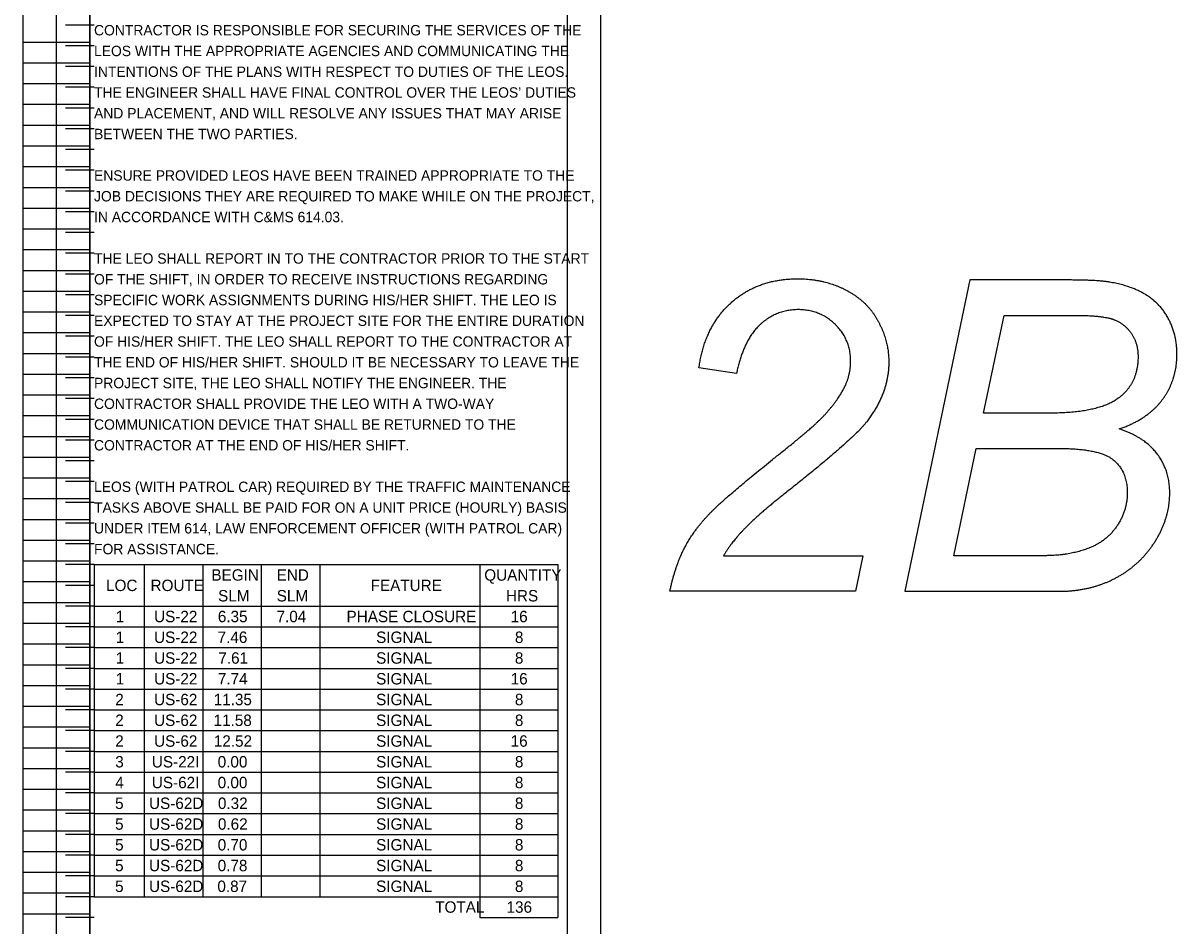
# Model space of a CAD drawing. Extents: x 12522 to 13018, y 1124 to 1902.
# Drawn here: x 12563.34 to 12578.9, y 1732.59 to 1744.77 of the extents above; entities that cross this region are included whole.
import ezdxf

# ---------------------------------------------------------------- set-up
doc = ezdxf.new("R2010")
doc.units = 0
for name, color, linetype in [('SC_Scratch1', 7, 'Continuous'), ('SH_Data', 7, 'Continuous'), ('SH_Text', 7, 'Continuous')]:
    doc.layers.add(name, color=color, linetype=linetype)

msp = doc.modelspace()

# ---------------------------------------------------------------- linework, layer by layer
at = {"layer": 'SC_Scratch1'}
for p, q in [((12564.236, 1769.381), (12564.236, 1728.831)), ((12563.336, 1728.831), (12563.336, 1748.991)), ((12563.336, 1728.831), (12563.336, 1748.991)), ((12564.236, 1728.831), (12564.236, 1748.991)), ((12564.236, 1728.831), (12564.236, 1748.991)), ((12564.293, 1744.741), (12563.909, 1744.741)), ((12563.336, 1744.511), (12564.236, 1744.511)), ((12563.336, 1744.511), (12564.236, 1744.511)), ((12564.293, 1744.461), (12563.909, 1744.461)), ((12563.336, 1744.231), (12564.236, 1744.231)), ((12563.336, 1744.231), (12564.236, 1744.231)), ((12564.293, 1744.181), (12563.909, 1744.181)), ((12563.336, 1743.951), (12564.236, 1743.951)), ((12563.336, 1743.951), (12564.236, 1743.951)), ((12564.293, 1743.901), (12563.909, 1743.901)), ((12563.336, 1743.671), (12564.236, 1743.671)), ((12563.336, 1743.671), (12564.236, 1743.671)), ((12564.293, 1743.621), (12563.909, 1743.621)), ((12563.336, 1743.391), (12564.236, 1743.391)), ((12563.336, 1743.391), (12564.236, 1743.391)), ((12564.293, 1743.341), (12563.909, 1743.341)), ((12563.336, 1743.111), (12564.236, 1743.111)), ((12563.336, 1743.111), (12564.236, 1743.111)), ((12564.293, 1743.061), (12563.909, 1743.061)), ((12563.336, 1742.831), (12564.236, 1742.831)), ((12563.336, 1742.831), (12564.236, 1742.831)), ((12564.293, 1742.781), (12563.909, 1742.781)), ((12563.336, 1742.551), (12564.236, 1742.551)), ((12563.336, 1742.551), (12564.236, 1742.551)), ((12564.293, 1742.501), (12563.909, 1742.501)), ((12563.336, 1742.271), (12564.236, 1742.271)), ((12563.336, 1742.271), (12564.236, 1742.271)), ((12564.293, 1742.221), (12563.909, 1742.221)), ((12563.336, 1741.991), (12564.236, 1741.991)), ((12563.336, 1741.991), (12564.236, 1741.991)), ((12564.293, 1741.941), (12563.909, 1741.941)), ((12563.336, 1741.711), (12564.236, 1741.711)), ((12563.336, 1741.711), (12564.236, 1741.711)), ((12564.293, 1741.661), (12563.909, 1741.661)), ((12563.336, 1741.431), (12564.236, 1741.431)), ((12563.336, 1741.431), (12564.236, 1741.431)), ((12564.293, 1741.381), (12563.909, 1741.381)), ((12563.336, 1741.151), (12564.236, 1741.151)), ((12563.336, 1741.151), (12564.236, 1741.151)), ((12564.293, 1741.101), (12563.909, 1741.101)), ((12563.336, 1740.871), (12564.236, 1740.871)), ((12563.336, 1740.871), (12564.236, 1740.871)), ((12564.293, 1740.821), (12563.909, 1740.821)), ((12563.336, 1740.591), (12564.236, 1740.591)), ((12563.336, 1740.591), (12564.236, 1740.591)), ((12564.293, 1740.541), (12563.909, 1740.541)), ((12563.336, 1740.311), (12564.236, 1740.311)), ((12563.336, 1740.311), (12564.236, 1740.311)), ((12564.293, 1740.261), (12563.909, 1740.261)), ((12563.336, 1740.031), (12564.236, 1740.031)), ((12563.336, 1740.031), (12564.236, 1740.031)), ((12572.959, 1740.039), (12572.453, 1740.114)), ((12572.959, 1740.039), (12572.453, 1740.114)), ((12564.293, 1739.981), (12563.909, 1739.981)), ((12563.336, 1739.751), (12564.236, 1739.751)), ((12563.336, 1739.751), (12564.236, 1739.751)), ((12564.293, 1739.701), (12563.909, 1739.701)), ((12563.336, 1739.471), (12564.236, 1739.471)), ((12563.336, 1739.471), (12564.236, 1739.471)), ((12564.293, 1739.421), (12563.909, 1739.421)), ((12563.336, 1739.191), (12564.236, 1739.191)), ((12563.336, 1739.191), (12564.236, 1739.191)), ((12564.293, 1739.141), (12563.909, 1739.141)), ((12563.336, 1738.911), (12564.236, 1738.911)), ((12563.336, 1738.911), (12564.236, 1738.911)), ((12564.293, 1738.861), (12563.909, 1738.861)), ((12563.336, 1738.631), (12564.236, 1738.631)), ((12563.336, 1738.631), (12564.236, 1738.631)), ((12564.293, 1738.581), (12563.909, 1738.581)), ((12563.336, 1738.351), (12564.236, 1738.351)), ((12563.336, 1738.351), (12564.236, 1738.351)), ((12564.293, 1738.301), (12563.909, 1738.301)), ((12563.336, 1738.071), (12564.236, 1738.071)), ((12563.336, 1738.071), (12564.236, 1738.071)), ((12564.293, 1738.021), (12563.909, 1738.021)), ((12563.336, 1737.791), (12564.236, 1737.791)), ((12563.336, 1737.791), (12564.236, 1737.791)), ((12564.293, 1737.741), (12563.909, 1737.741)), ((12563.336, 1737.511), (12564.236, 1737.511)), ((12563.336, 1737.511), (12564.236, 1737.511)), ((12564.293, 1737.461), (12563.909, 1737.461)), ((12563.336, 1737.231), (12564.236, 1737.231)), ((12563.336, 1737.231), (12564.236, 1737.231)), ((12564.293, 1737.181), (12563.909, 1737.181)), ((12563.336, 1736.951), (12564.236, 1736.951)), ((12563.336, 1736.951), (12564.236, 1736.951)), ((12564.293, 1736.901), (12563.909, 1736.901)), ((12563.336, 1736.671), (12564.236, 1736.671)), ((12563.336, 1736.671), (12564.236, 1736.671)), ((12564.293, 1736.621), (12563.909, 1736.621)), ((12563.336, 1736.391), (12564.236, 1736.391)), ((12563.336, 1736.391), (12564.236, 1736.391)), ((12564.293, 1736.341), (12563.909, 1736.341)), ((12563.336, 1736.111), (12564.236, 1736.111)), ((12563.336, 1736.111), (12564.236, 1736.111)), ((12564.293, 1736.061), (12563.909, 1736.061)), ((12563.336, 1735.831), (12564.236, 1735.831)), ((12563.336, 1735.831), (12564.236, 1735.831)), ((12564.293, 1735.781), (12563.909, 1735.781)), ((12563.336, 1735.551), (12564.236, 1735.551)), ((12563.336, 1735.551), (12564.236, 1735.551)), ((12564.293, 1735.501), (12563.909, 1735.501)), ((12563.336, 1735.271), (12564.236, 1735.271)), ((12563.336, 1735.271), (12564.236, 1735.271)), ((12564.293, 1735.221), (12563.909, 1735.221)), ((12563.336, 1734.991), (12564.236, 1734.991)), ((12563.336, 1734.991), (12564.236, 1734.991)), ((12564.293, 1734.941), (12563.909, 1734.941)), ((12563.336, 1734.711), (12564.236, 1734.711)), ((12563.336, 1734.711), (12564.236, 1734.711)), ((12564.293, 1734.661), (12563.909, 1734.661)), ((12563.336, 1734.431), (12564.236, 1734.431)), ((12563.336, 1734.431), (12564.236, 1734.431)), ((12564.293, 1734.381), (12563.909, 1734.381)), ((12563.336, 1734.151), (12564.236, 1734.151)), ((12563.336, 1734.151), (12564.236, 1734.151)), ((12564.293, 1734.101), (12563.909, 1734.101)), ((12563.336, 1733.871), (12564.236, 1733.871)), ((12563.336, 1733.871), (12564.236, 1733.871)), ((12564.293, 1733.821), (12563.909, 1733.821)), ((12563.336, 1733.591), (12564.236, 1733.591)), ((12563.336, 1733.591), (12564.236, 1733.591)), ((12564.293, 1733.541), (12563.909, 1733.541)), ((12563.336, 1733.311), (12564.236, 1733.311)), ((12563.336, 1733.311), (12564.236, 1733.311)), ((12564.293, 1733.261), (12563.909, 1733.261)), ((12563.336, 1733.031), (12564.236, 1733.031)), ((12563.336, 1733.031), (12564.236, 1733.031)), ((12564.293, 1732.981), (12563.909, 1732.981)), ((12563.336, 1732.751), (12564.236, 1732.751)), ((12563.336, 1732.751), (12564.236, 1732.751)), ((12564.293, 1732.701), (12563.909, 1732.701))]:
    msp.add_line(p, q, dxfattribs=at)
for points in [[(12563.786, 1748.991), (12571.126, 1748.991), (12571.126, 1728.831), (12563.786, 1728.831)], [(12564.236, 1748.991), (12570.676, 1748.991), (12570.676, 1728.831), (12564.236, 1728.831)], [(12564.236, 1748.991), (12570.676, 1748.991), (12570.676, 1728.831), (12564.236, 1728.831)]]:
    msp.add_lwpolyline(points, close=True, dxfattribs=at)
for points in [[(12577.45, 1741.301), (12576.109, 1741.301), (12575.232, 1737.101), (12577.313, 1737.101)], [(12577.45, 1741.301), (12576.109, 1741.301), (12575.232, 1737.101), (12577.313, 1737.101)], [(12577.188, 1739.505), (12576.293, 1739.505), (12576.568, 1740.824), (12577.507, 1740.824)], [(12577.188, 1739.505), (12576.293, 1739.505), (12576.568, 1740.824), (12577.507, 1740.824)], [(12576.883, 1737.578), (12575.891, 1737.578), (12576.193, 1739.028), (12577.31, 1739.028)], [(12576.883, 1737.578), (12575.891, 1737.578), (12576.193, 1739.028), (12577.31, 1739.028)], [(12572.785, 1737.578), (12574.665, 1737.578), (12574.565, 1737.101), (12572.06, 1737.101)], [(12572.785, 1737.578), (12574.665, 1737.578), (12574.565, 1737.101), (12572.06, 1737.101)]]:
    msp.add_lwpolyline(points, dxfattribs=at)
for points in [[(12572.887, 1740.995), (12573.247, 1741.317), (12573.782, 1741.317)], [(12572.887, 1740.995), (12573.247, 1741.317), (12573.782, 1741.317)], [(12573.782, 1741.317), (12574.141, 1741.317), (12574.431, 1741.168)], [(12573.782, 1741.317), (12574.141, 1741.317), (12574.431, 1741.168)], [(12577.994, 1741.272), (12577.816, 1741.301), (12577.45, 1741.301)], [(12577.994, 1741.272), (12577.816, 1741.301), (12577.45, 1741.301)], [(12578.483, 1741.101), (12578.283, 1741.223), (12577.994, 1741.272)], [(12578.483, 1741.101), (12578.283, 1741.223), (12577.994, 1741.272)], [(12574.431, 1741.168), (12574.722, 1741.019), (12574.868, 1740.75)], [(12574.431, 1741.168), (12574.722, 1741.019), (12574.868, 1740.75)], [(12578.791, 1740.769), (12578.682, 1740.98), (12578.483, 1741.101)], [(12578.791, 1740.769), (12578.682, 1740.98), (12578.483, 1741.101)], [(12572.453, 1740.114), (12572.528, 1740.672), (12572.887, 1740.995)], [(12572.453, 1740.114), (12572.528, 1740.672), (12572.887, 1740.995)], [(12573.791, 1740.901), (12573.495, 1740.901), (12573.274, 1740.696)], [(12573.791, 1740.901), (12573.495, 1740.901), (12573.274, 1740.696)], [(12574.294, 1740.699), (12574.089, 1740.901), (12573.791, 1740.901)], [(12574.294, 1740.699), (12574.089, 1740.901), (12573.791, 1740.901)], [(12577.507, 1740.824), (12577.909, 1740.824), (12578.055, 1740.765)], [(12577.507, 1740.824), (12577.909, 1740.824), (12578.055, 1740.765)], [(12573.274, 1740.696), (12573.054, 1740.491), (12572.959, 1740.039)], [(12573.274, 1740.696), (12573.054, 1740.491), (12572.959, 1740.039)], [(12574.499, 1740.208), (12574.499, 1740.497), (12574.294, 1740.699)], [(12574.499, 1740.208), (12574.499, 1740.497), (12574.294, 1740.699)], [(12574.868, 1740.75), (12575.014, 1740.481), (12575.014, 1740.194)], [(12574.868, 1740.75), (12575.014, 1740.481), (12575.014, 1740.194)], [(12578.055, 1740.765), (12578.201, 1740.706), (12578.288, 1740.577)], [(12578.055, 1740.765), (12578.201, 1740.706), (12578.288, 1740.577)], [(12578.901, 1740.303), (12578.901, 1740.558), (12578.791, 1740.769)], [(12578.901, 1740.303), (12578.901, 1740.558), (12578.791, 1740.769)], [(12578.288, 1740.577), (12578.376, 1740.447), (12578.376, 1740.269)], [(12578.288, 1740.577), (12578.376, 1740.447), (12578.376, 1740.269)], [(12574.433, 1739.89), (12574.499, 1740.036), (12574.499, 1740.208)], [(12574.433, 1739.89), (12574.499, 1740.036), (12574.499, 1740.208)], [(12575.014, 1740.194), (12575.014, 1739.776), (12574.716, 1739.389)], [(12575.014, 1740.194), (12575.014, 1739.776), (12574.716, 1739.389)], [(12578.376, 1740.269), (12578.376, 1739.896), (12578.102, 1739.7)], [(12578.376, 1740.269), (12578.376, 1739.896), (12578.102, 1739.7)], [(12578.709, 1739.692), (12578.901, 1739.956), (12578.901, 1740.303)], [(12578.709, 1739.692), (12578.901, 1739.956), (12578.901, 1740.303)], [(12574.121, 1739.452), (12574.335, 1739.676), (12574.433, 1739.89)], [(12574.121, 1739.452), (12574.335, 1739.676), (12574.433, 1739.89)], [(12578.102, 1739.7), (12577.829, 1739.505), (12577.188, 1739.505)], [(12578.102, 1739.7), (12577.829, 1739.505), (12577.188, 1739.505)], [(12578.123, 1739.291), (12578.517, 1739.428), (12578.709, 1739.692)], [(12578.123, 1739.291), (12578.517, 1739.428), (12578.709, 1739.692)], [(12573.564, 1738.974), (12573.971, 1739.298), (12574.121, 1739.452)], [(12573.564, 1738.974), (12573.971, 1739.298), (12574.121, 1739.452)], [(12574.716, 1739.389), (12574.533, 1739.149), (12573.639, 1738.442)], [(12574.716, 1739.389), (12574.533, 1739.149), (12573.639, 1738.442)], [(12578.635, 1738.954), (12578.465, 1739.179), (12578.123, 1739.291)], [(12578.635, 1738.954), (12578.465, 1739.179), (12578.123, 1739.291)], [(12572.659, 1738.211), (12572.894, 1738.439), (12573.564, 1738.974)], [(12572.659, 1738.211), (12572.894, 1738.439), (12573.564, 1738.974)], [(12577.31, 1739.028), (12577.853, 1739.028), (12578.042, 1738.875)], [(12577.31, 1739.028), (12577.853, 1739.028), (12578.042, 1738.875)], [(12578.804, 1738.429), (12578.804, 1738.73), (12578.635, 1738.954)], [(12578.804, 1738.429), (12578.804, 1738.73), (12578.635, 1738.954)], [(12578.042, 1738.875), (12578.231, 1738.722), (12578.231, 1738.427)], [(12578.042, 1738.875), (12578.231, 1738.722), (12578.231, 1738.427)], [(12573.639, 1738.442), (12573.255, 1738.139), (12573.067, 1737.944)], [(12573.639, 1738.442), (12573.255, 1738.139), (12573.067, 1737.944)], [(12578.231, 1738.427), (12578.231, 1738.23), (12578.133, 1738.05)], [(12578.231, 1738.427), (12578.231, 1738.23), (12578.133, 1738.05)], [(12578.601, 1737.765), (12578.804, 1738.083), (12578.804, 1738.429)], [(12578.601, 1737.765), (12578.804, 1738.083), (12578.804, 1738.429)], [(12572.282, 1737.73), (12572.424, 1737.984), (12572.659, 1738.211)], [(12572.282, 1737.73), (12572.424, 1737.984), (12572.659, 1738.211)], [(12578.133, 1738.05), (12578.035, 1737.87), (12577.863, 1737.759)], [(12578.133, 1738.05), (12578.035, 1737.87), (12577.863, 1737.759)], [(12573.067, 1737.944), (12572.879, 1737.75), (12572.785, 1737.578)], [(12573.067, 1737.944), (12572.879, 1737.75), (12572.785, 1737.578)], [(12572.06, 1737.101), (12572.14, 1737.476), (12572.282, 1737.73)], [(12572.06, 1737.101), (12572.14, 1737.476), (12572.282, 1737.73)], [(12577.863, 1737.759), (12577.691, 1737.649), (12577.415, 1737.604)], [(12577.863, 1737.759), (12577.691, 1737.649), (12577.415, 1737.604)], [(12578.062, 1737.274), (12578.397, 1737.447), (12578.601, 1737.765)], [(12578.062, 1737.274), (12578.397, 1737.447), (12578.601, 1737.765)], [(12577.415, 1737.604), (12577.278, 1737.578), (12576.883, 1737.578)], [(12577.415, 1737.604), (12577.278, 1737.578), (12576.883, 1737.578)], [(12577.313, 1737.101), (12577.726, 1737.101), (12578.062, 1737.274)], [(12577.313, 1737.101), (12577.726, 1737.101), (12578.062, 1737.274)]]:
    msp.add_open_spline(points, degree=2, dxfattribs=at)
at = {"layer": 'SH_Data'}
for p, q in [((12564.293, 1737.461), (12570.551, 1737.461)), ((12564.293, 1737.461), (12564.293, 1732.981)), ((12564.968, 1737.461), (12564.968, 1732.981)), ((12565.759, 1737.461), (12565.759, 1732.981)), ((12566.549, 1737.461), (12566.549, 1732.981)), ((12567.34, 1737.461), (12567.34, 1732.981)), ((12569.497, 1737.461), (12569.497, 1732.701)), ((12570.551, 1737.461), (12570.551, 1732.701)), ((12564.293, 1736.901), (12570.551, 1736.901)), ((12564.293, 1736.621), (12570.551, 1736.621)), ((12564.293, 1736.341), (12570.551, 1736.341)), ((12564.293, 1736.061), (12570.551, 1736.061)), ((12564.293, 1735.781), (12570.551, 1735.781)), ((12564.293, 1735.501), (12570.551, 1735.501)), ((12564.293, 1735.221), (12570.551, 1735.221)), ((12564.293, 1734.941), (12570.551, 1734.941)), ((12564.293, 1734.661), (12570.551, 1734.661)), ((12564.293, 1734.381), (12570.551, 1734.381)), ((12564.293, 1734.101), (12570.551, 1734.101)), ((12564.293, 1733.821), (12570.551, 1733.821)), ((12564.293, 1733.541), (12570.551, 1733.541)), ((12564.293, 1733.261), (12570.551, 1733.261)), ((12564.293, 1732.981), (12570.551, 1732.981)), ((12569.497, 1732.701), (12570.551, 1732.701))]:
    msp.add_line(p, q, dxfattribs=at)

# ---------------------------------------------------------------- texts
at = {"layer": 'SH_Text'}
for s, height, p in [('CONTRACTOR IS RESPONSIBLE FOR SECURING THE SERVICES OF THE ', 0.14, (12564.293, 1744.601)), ('LEOS WITH THE APPROPRIATE AGENCIES AND COMMUNICATING THE ', 0.14, (12564.293, 1744.321)), ('INTENTIONS OF THE PLANS WITH RESPECT TO DUTIES OF THE LEOS. ', 0.14, (12564.293, 1744.041)), ('THE ENGINEER SHALL HAVE FINAL CONTROL OVER THE LEOS’ DUTIES ', 0.14, (12564.293, 1743.761)), ('AND PLACEMENT, AND WILL RESOLVE ANY ISSUES THAT MAY ARISE ', 0.14, (12564.293, 1743.481)), ('BETWEEN THE TWO PARTIES. ', 0.14, (12564.293, 1743.201)), ('ENSURE PROVIDED LEOS HAVE BEEN TRAINED APPROPRIATE TO THE ', 0.14, (12564.293, 1742.641)), ('JOB DECISIONS THEY ARE REQUIRED TO MAKE WHILE ON THE PROJECT, ', 0.14, (12564.293, 1742.361)), ('IN ACCORDANCE WITH C&MS 614.03. ', 0.14, (12564.293, 1742.081)), ('THE LEO SHALL REPORT IN TO THE CONTRACTOR PRIOR TO THE START ', 0.14, (12564.293, 1741.521)), ('OF THE SHIFT, IN ORDER TO RECEIVE INSTRUCTIONS REGARDING ', 0.14, (12564.293, 1741.241)), ('SPECIFIC WORK ASSIGNMENTS DURING HIS/HER SHIFT. THE LEO IS ', 0.14, (12564.293, 1740.961)), ('EXPECTED TO STAY AT THE PROJECT SITE FOR THE ENTIRE DURATION ', 0.14, (12564.293, 1740.681)), ('OF HIS/HER SHIFT. THE LEO SHALL REPORT TO THE CONTRACTOR AT ', 0.14, (12564.293, 1740.401)), ('THE END OF HIS/HER SHIFT. SHOULD IT BE NECESSARY TO LEAVE THE ', 0.14, (12564.293, 1740.121)), ('PROJECT SITE, THE LEO SHALL NOTIFY THE ENGINEER. THE ', 0.14, (12564.293, 1739.841)), ('CONTRACTOR SHALL PROVIDE THE LEO WITH A TWO-WAY ', 0.14, (12564.293, 1739.561)), ('COMMUNICATION DEVICE THAT SHALL BE RETURNED TO THE ', 0.14, (12564.293, 1739.281)), ('CONTRACTOR AT THE END OF HIS/HER SHIFT.', 0.14, (12564.293, 1739.001)), ('LEOS (WITH PATROL CAR) REQUIRED BY THE TRAFFIC MAINTENANCE ', 0.14, (12564.293, 1738.441)), ('TASKS ABOVE SHALL BE PAID FOR ON A UNIT PRICE (HOURLY) BASIS ', 0.14, (12564.293, 1738.161)), ('UNDER ITEM 614, LAW ENFORCEMENT OFFICER (WITH PATROL CAR) ', 0.14, (12564.293, 1737.881)), ('FOR ASSISTANCE. ', 0.14, (12564.293, 1737.601)), ('BEGIN', 0.154, (12565.876, 1737.244)), ('END', 0.154, (12566.756, 1737.244)), ('QUANTITY', 0.154, (12569.557, 1737.244)), ('LOC', 0.154, (12564.455, 1737.104)), ('ROUTE', 0.154, (12565.055, 1737.104)), ('FEATURE', 0.154, (12568.024, 1737.104)), ('SLM', 0.154, (12565.966, 1736.964)), ('SLM', 0.154, (12566.757, 1736.964)), ('HRS', 0.154, (12569.849, 1736.964)), ('1', 0.154, (12564.585, 1736.684)), ('US-22', 0.154, (12565.103, 1736.684)), ('6.35', 0.154, (12565.963, 1736.684)), ('7.04', 0.154, (12566.755, 1736.684)), ('PHASE CLOSURE', 0.154, (12567.699, 1736.684)), ('16', 0.154, (12569.913, 1736.684)), ('1', 0.154, (12564.585, 1736.404)), ('US-22', 0.154, (12565.103, 1736.404)), ('7.46', 0.154, (12565.96, 1736.404)), ('SIGNAL', 0.154, (12568.098, 1736.404)), ('8', 0.154, (12569.97, 1736.404)), ('1', 0.154, (12564.585, 1736.124)), ('US-22', 0.154, (12565.103, 1736.124)), ('7.61', 0.154, (12565.97, 1736.124)), ('SIGNAL', 0.154, (12568.098, 1736.124)), ('8', 0.154, (12569.97, 1736.124)), ('1', 0.154, (12564.585, 1735.844)), ('US-22', 0.154, (12565.103, 1735.844)), ('7.74', 0.154, (12565.964, 1735.844)), ('SIGNAL', 0.154, (12568.098, 1735.844)), ('16', 0.154, (12569.913, 1735.844)), ('2', 0.154, (12564.579, 1735.564)), ('US-62', 0.154, (12565.103, 1735.564)), ('11.35', 0.154, (12565.907, 1735.564)), ('SIGNAL', 0.154, (12568.098, 1735.564)), ('8', 0.154, (12569.97, 1735.564)), ('2', 0.154, (12564.579, 1735.284)), ('US-62', 0.154, (12565.103, 1735.284)), ('11.58', 0.154, (12565.906, 1735.284)), ('SIGNAL', 0.154, (12568.098, 1735.284)), ('8', 0.154, (12569.97, 1735.284)), ('2', 0.154, (12564.579, 1735.004)), ('US-62', 0.154, (12565.103, 1735.004)), ('12.52', 0.154, (12565.909, 1735.004)), ('SIGNAL', 0.154, (12568.098, 1735.004)), ('16', 0.154, (12569.913, 1735.004)), ('3', 0.154, (12564.579, 1734.724)), ('US-22I', 0.154, (12565.073, 1734.724)), ('0.00', 0.154, (12565.961, 1734.724)), ('SIGNAL', 0.154, (12568.098, 1734.724)), ('8', 0.154, (12569.97, 1734.724)), ('4', 0.154, (12564.579, 1734.444)), ('US-62I', 0.154, (12565.073, 1734.444)), ('0.00', 0.154, (12565.961, 1734.444)), ('SIGNAL', 0.154, (12568.098, 1734.444)), ('8', 0.154, (12569.97, 1734.444)), ('5', 0.154, (12564.577, 1734.164)), ('US-62D', 0.154, (12565.035, 1734.164)), ('0.32', 0.154, (12565.964, 1734.164)), ('SIGNAL', 0.154, (12568.098, 1734.164)), ('8', 0.154, (12569.97, 1734.164)), ('5', 0.154, (12564.577, 1733.884)), ('US-62D', 0.154, (12565.035, 1733.884)), ('0.62', 0.154, (12565.964, 1733.884)), ('SIGNAL', 0.154, (12568.098, 1733.884)), ('8', 0.154, (12569.97, 1733.884)), ('5', 0.154, (12564.577, 1733.604)), ('US-62D', 0.154, (12565.035, 1733.604)), ('0.70', 0.154, (12565.961, 1733.604)), ('SIGNAL', 0.154, (12568.098, 1733.604)), ('8', 0.154, (12569.97, 1733.604)), ('5', 0.154, (12564.577, 1733.324)), ('US-62D', 0.154, (12565.035, 1733.324)), ('0.78', 0.154, (12565.961, 1733.324)), ('SIGNAL', 0.154, (12568.098, 1733.324)), ('8', 0.154, (12569.97, 1733.324)), ('5', 0.154, (12564.577, 1733.044)), ('US-62D', 0.154, (12565.035, 1733.044)), ('0.87', 0.154, (12565.957, 1733.044)), ('SIGNAL', 0.154, (12568.098, 1733.044)), ('8', 0.154, (12569.97, 1733.044)), ('TOTAL', 0.154, (12568.895, 1732.764)), ('136', 0.154, (12569.858, 1732.764))]:
    msp.add_text(s, height=height, dxfattribs=at).set_placement(p)

doc.saveas('drawing.dxf')
